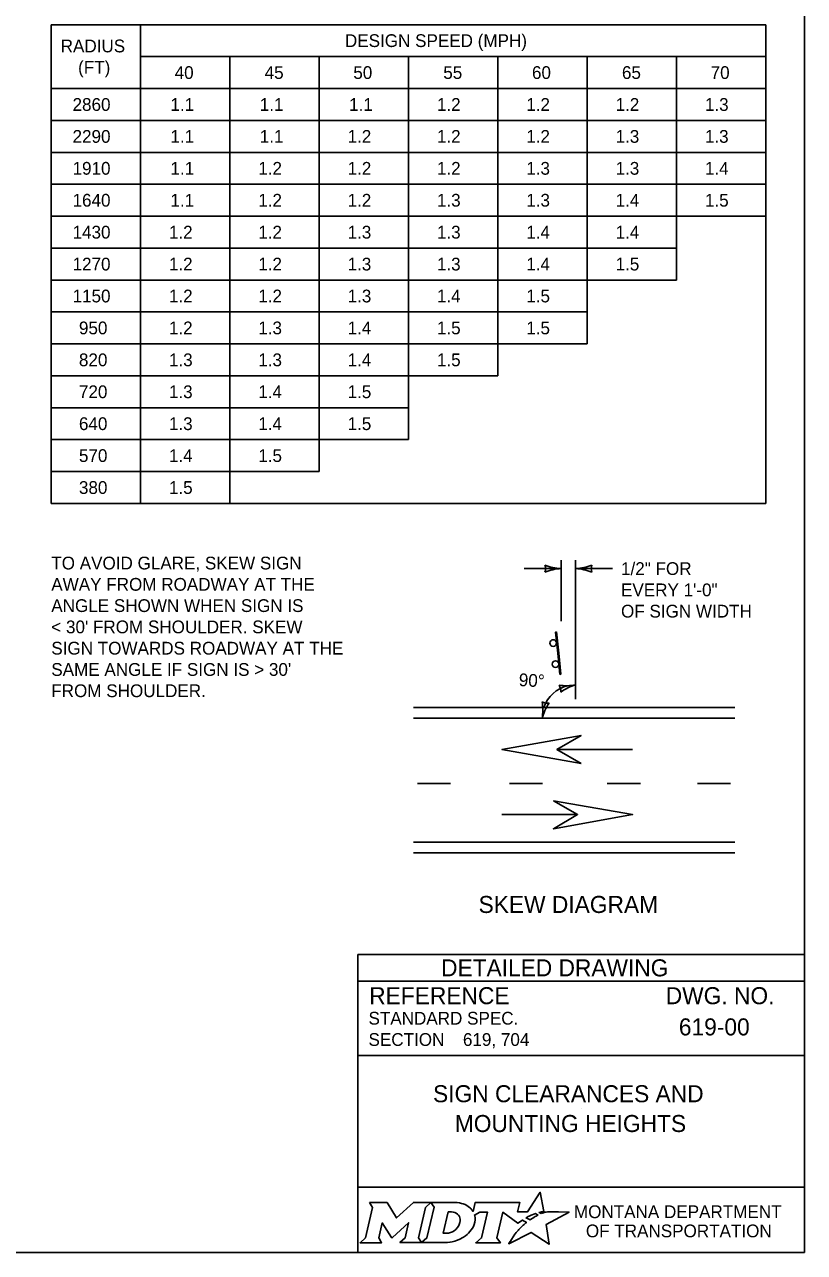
# Model space of a CAD drawing. Extents: x 49991.4 to 50021, y 49987.6 to 50011.4.
# Drawn here: x 50013.08 to 50016.75, y 49987.8 to 49993.57 of the extents above; entities that cross this region are included whole.
import ezdxf

# ---------------------------------------------------------------- set-up
doc = ezdxf.new("R2010")
doc.units = 0
for name, color, linetype in [('Default', 7, 'Continuous'), ('Level 1', 7, 'Continuous'), ('Level 2', 7, 'Continuous'), ('Level 3', 7, 'Continuous'), ('Level 5', 7, 'Continuous')]:
    doc.layers.add(name, color=color, linetype=linetype)

msp = doc.modelspace()

# ---------------------------------------------------------------- linework, layer by layer
at = {"layer": 'Default'}
for points in [[(50015.5126, 49987.9811), (50015.5023, 49987.9867), (50015.5139, 49987.9895), (50015.5255, 49987.9915), (50015.5081, 49988.0816), (50015.4486, 49987.9903), (50015.4013, 49987.9896), (50015.4116, 49988.0337), (50015.2024, 49988.0338), (50015.1923, 49987.9913), (50015.1865, 49987.9996)], [(50014.7056, 49988.0338), (50014.7197, 49988.0104), (50014.6862, 49987.8671), (50014.6605, 49987.8446), (50014.7621, 49987.8446), (50014.7486, 49987.8674), (50014.7648, 49987.9375), (50014.8085, 49987.8685), (50014.8138, 49987.8685), (50014.8889, 49987.938), (50014.8725, 49987.8669), (50014.8478, 49987.8449), (50014.9494, 49987.8449), (50014.9356, 49987.8682), (50014.9688, 49988.0106)], [(50014.9688, 49988.0106), (50014.9941, 49988.0338), (50014.9117, 49988.0338), (50014.8321, 49987.9608), (50014.7876, 49988.0335), (50014.7056, 49988.0338)], [(50015.1077, 49988.0338), (50014.9941, 49988.0338), (50015.0088, 49988.0109), (50014.9749, 49987.8671), (50014.9494, 49987.8449), (50015.06, 49987.8449)], [(50015.1317, 49987.9471), (50015.1305, 49987.939), (50015.1273, 49987.9297), (50015.1231, 49987.9215), (50015.1175, 49987.914), (50015.111, 49987.9071), (50015.1031, 49987.9008), (50015.0948, 49987.8961), (50015.0857, 49987.8922), (50015.0766, 49987.8899), (50015.0674, 49987.889), (50015.0515, 49987.889), (50015.0751, 49987.989), (50015.0911, 49987.989), (50015.0987, 49987.9884), (50015.1063, 49987.9865), (50015.1129, 49987.9835), (50015.119, 49987.9793), (50015.1238, 49987.9743), (50015.1275, 49987.9683), (50015.1302, 49987.9621), (50015.1318, 49987.9547), (50015.1318, 49987.9517), (50015.1317, 49987.9471)], [(50015.1991, 49987.9747), (50015.2237, 49987.9878), (50015.2606, 49987.9878), (50015.232, 49987.8673), (50015.2045, 49987.8446), (50015.3207, 49987.8446), (50015.3037, 49987.8675), (50015.3319, 49987.9877), (50015.4032, 49987.936), (50015.4243, 49987.9511), (50015.444, 49987.9402)], [(50015.3882, 49987.8843), (50015.3729, 49987.8599), (50015.3682, 49987.8524), (50015.3624, 49987.8438), (50015.3601, 49987.8395), (50015.4654, 49987.8926), (50015.5493, 49987.8375), (50015.5362, 49987.9302), (50015.6431, 49987.9886), (50015.5938, 49987.9894), (50015.5637, 49987.9898), (50015.5429, 49987.9901), (50015.5361, 49987.9886), (50015.5312, 49987.9874), (50015.5228, 49987.9851), (50015.5126, 49987.9811)], [(50015.4622, 49987.9535), (50015.4598, 49987.9518), (50015.4415, 49987.9614), (50015.4518, 49987.9671), (50015.4559, 49987.9693), (50015.4645, 49987.9733), (50015.4702, 49987.9759), (50015.4781, 49987.9789), (50015.4854, 49987.9816), (50015.4972, 49987.9742), (50015.4932, 49987.9721), (50015.4886, 49987.9696), (50015.4844, 49987.9674), (50015.4794, 49987.9645), (50015.4775, 49987.9634), (50015.4748, 49987.9618), (50015.4723, 49987.9604), (50015.47, 49987.9588), (50015.4674, 49987.957), (50015.4647, 49987.9552), (50015.4622, 49987.9535)], [(50015.1057, 49987.8522), (50015.1141, 49987.8548), (50015.1271, 49987.8602), (50015.1475, 49987.8712)], [(50015.4021, 49987.9004), (50015.4021, 49987.9004)]]:
    msp.add_lwpolyline(points, dxfattribs=at)
for centre, radius, start, end in [((50015.1308, 49987.9554), 0.0709, 339.53292, 15.85821), ((50015.0868, 49987.9727), 0.1183, 300.91025, 339.13831)]:
    msp.add_arc(centre, radius, start, end, dxfattribs=at)
for centre, major_axis, ratio, start_param, end_param in [((50015.1056, 49987.9864), (0.0834, -0.0037), 0.568097, 0.61298, 1.570796), ((50015.1612, 49987.9937), (0.0361, -0.0295), 0.469099, 1.225588, 1.570796), ((50015.4119, 49987.9106), (-0.0098, -0.0102), 0.016458, 3.141593, 6.279097), ((50015.4329, 49987.9305), (-0.0112, -0.0097), 0.021651, 3.157348, 6.283185), ((50015.0603, 49987.9932), (0, 0.1484), 0.987302, 3.139398, 3.456847), ((50015.3952, 49987.8923), (-0.00694, -0.00806), 0.008222, 0, 3.137361)]:
    msp.add_ellipse(centre, major_axis=major_axis, ratio=ratio, start_param=start_param, end_param=end_param, dxfattribs=at)
at = {"layer": 'Level 1'}
for p, q in [((50015.5795, 49990.7139), (50015.5845, 49990.7145)), ((50015.5795, 49990.7139), (50015.5899, 49990.6148)), ((50015.5801, 49990.714), (50015.5905, 49990.6148)), ((50015.5807, 49990.7141), (50015.5911, 49990.6149)), ((50015.5813, 49990.7141), (50015.5917, 49990.615)), ((50015.582, 49990.7142), (50015.5924, 49990.615)), ((50015.5826, 49990.7143), (50015.593, 49990.6151)), ((50015.5833, 49990.7143), (50015.5937, 49990.6152)), ((50015.5839, 49990.7144), (50015.5943, 49990.6152)), ((50015.5845, 49990.7145), (50015.5949, 49990.6153)), ((50015.5949, 49990.6153), (50015.5899, 49990.6148)), ((50015.5949, 49990.6153), (50015.5899, 49990.6148)), ((50015.6003, 49990.5155), (50015.5899, 49990.6148)), ((50015.6009, 49990.5156), (50015.5905, 49990.6148)), ((50015.6015, 49990.5157), (50015.5911, 49990.6149)), ((50015.6021, 49990.5157), (50015.5917, 49990.615)), ((50015.6028, 49990.5158), (50015.5924, 49990.615)), ((50015.6034, 49990.5159), (50015.593, 49990.6151)), ((50015.6041, 49990.5159), (50015.5937, 49990.6152)), ((50015.6047, 49990.516), (50015.5943, 49990.6152)), ((50015.6053, 49990.5161), (50015.5949, 49990.6153)), ((50015.6003, 49990.5155), (50015.6053, 49990.5161)), ((50016.4225, 49990.359), (50014.9126, 49990.359)), ((50015.6742, 49990.309), (50014.9126, 49990.309)), ((50016.4225, 49990.309), (50015.6742, 49990.309)), ((50015.9421, 49990.1623), (50015.5863, 49990.1623)), ((50014.9308, 49990.0031), (50015.0864, 49990.0031)), ((50015.5188, 49990.0031), (50015.3632, 49990.0031)), ((50015.9788, 49990.0031), (50015.8232, 49990.0031)), ((50016.4026, 49990.0031), (50016.247, 49990.0031)), ((50015.3275, 49989.8566), (50015.6833, 49989.8566)), ((50015.3275, 49989.8562), (50015.6833, 49989.8562)), ((50014.9126, 49989.7263), (50016.4225, 49989.7263)), ((50014.9126, 49989.6763), (50016.4225, 49989.6763)), ((50016.7501, 49989.1988), (50014.6501, 49989.1988)), ((50014.6501, 49989.1988), (50014.6501, 49987.7988)), ((50016.7501, 49989.0738), (50014.6501, 49989.0738)), ((50016.3862, 49988.8587), (50016.3862, 49988.8587)), ((50015.1444, 49988.7993), (50015.1444, 49988.7993)), ((50016.7501, 49988.7238), (50014.6501, 49988.7238)), ((50015.7001, 49988.4747), (50015.7001, 49988.4747))]:
    msp.add_line(p, q, dxfattribs=at)
for points in [[(49999.3835, 49998.9992), (50016.7501, 49998.9992), (50016.7501, 49987.7988), (49999.3835, 49987.7988)], [(50015.7001, 49990.0963), (50015.3277, 49990.1619), (50015.7001, 49990.2279), (50015.5865, 49990.1619)], [(50015.5697, 49989.9218), (50015.9421, 49989.8562), (50015.5697, 49989.7902), (50015.6833, 49989.8562)]]:
    msp.add_lwpolyline(points, close=True, dxfattribs=at)
for centre in [(50015.5689, 49990.6627), (50015.5793, 49990.5634)]:
    msp.add_circle(centre, 0.0156, dxfattribs=at)
at = {"layer": 'Level 2'}
for p, q in [((50013.209, 49993.5684), (50016.569, 49993.5684)), ((50013.209, 49993.5684), (50013.209, 49991.3184)), ((50013.629, 49993.5684), (50013.629, 49991.3184)), ((50016.569, 49993.5684), (50016.569, 49991.3184)), ((50013.629, 49993.4184), (50016.569, 49993.4184)), ((50014.049, 49993.4184), (50014.049, 49991.3184)), ((50014.469, 49993.4184), (50014.469, 49991.4684)), ((50014.889, 49993.4184), (50014.889, 49991.6184)), ((50015.309, 49993.4184), (50015.309, 49991.9184)), ((50015.729, 49993.4184), (50015.729, 49992.0684)), ((50016.149, 49993.4184), (50016.149, 49992.3684)), ((50013.209, 49993.2684), (50016.569, 49993.2684)), ((50013.209, 49993.1184), (50016.569, 49993.1184)), ((50013.209, 49992.9684), (50016.569, 49992.9684)), ((50013.209, 49992.8184), (50016.569, 49992.8184)), ((50013.209, 49992.6684), (50016.569, 49992.6684)), ((50016.569, 49992.6684), (50016.149, 49992.6684)), ((50016.149, 49992.6684), (50016.149, 49992.3684)), ((50016.569, 49991.3184), (50016.569, 49992.6684)), ((50013.209, 49992.5184), (50016.149, 49992.5184)), ((50013.209, 49992.3684), (50016.149, 49992.3684)), ((50016.149, 49992.3684), (50015.729, 49992.3684)), ((50015.729, 49992.3684), (50015.729, 49992.0684)), ((50013.209, 49992.2184), (50015.729, 49992.2184)), ((50013.209, 49992.0684), (50015.729, 49992.0684)), ((50015.729, 49992.0684), (50015.309, 49992.0684)), ((50015.309, 49992.0684), (50015.309, 49991.9184)), ((50013.209, 49991.9184), (50015.309, 49991.9184)), ((50015.309, 49991.9184), (50014.889, 49991.9184)), ((50014.889, 49991.9184), (50014.889, 49991.6184)), ((50013.209, 49991.7684), (50014.889, 49991.7684)), ((50013.209, 49991.6184), (50014.889, 49991.6184)), ((50014.889, 49991.6184), (50014.469, 49991.6184)), ((50014.469, 49991.6184), (50014.469, 49991.4684)), ((50013.209, 49991.4684), (50014.469, 49991.4684)), ((50014.469, 49991.4684), (50014.049, 49991.4684)), ((50014.049, 49991.4684), (50014.049, 49991.3184)), ((50013.209, 49991.3184), (50016.569, 49991.3184)), ((50014.049, 49991.3184), (50016.569, 49991.3184)), ((50016.4225, 49989.7263), (50016.4225, 49989.7263))]:
    msp.add_line(p, q, dxfattribs=at)
at = {"layer": 'Level 3'}
for p, q in [((50015.6059, 49990.7658), (50015.6059, 49991.0524)), ((50015.6743, 49990.399), (50015.6743, 49991.0524)), ((50015.4325, 49991.0124), (50015.6059, 49991.0124)), ((50015.6743, 49991.0124), (50015.8477, 49991.0124))]:
    msp.add_line(p, q, dxfattribs=at)
for centre, radius, start, end in [((50015.6151, 49991.2345), 0.2223, 247.45601, 267.63952), ((50015.4777, 49991.0124), 0.0548, 342.13882, 17.86118), ((50015.6628, 49991.2451), 0.233, 272.82731, 292.07716), ((50015.8026, 49991.0124), 0.0548, 162.13882, 197.86118), ((50015.6174, 49990.7797), 0.233, 92.82731, 112.07716), ((50015.6652, 49990.7903), 0.2223, 67.45601, 87.63952), ((50015.6743, 49990.309), 0.1574, 103.39391, 161.48029), ((50015.6303, 49990.6843), 0.2223, 261.22568, 281.40919), ((50015.5498, 49990.4359), 0.0548, 355.90849, 31.63085), ((50015.7409, 49990.2431), 0.233, 106.59698, 125.84683), ((50015.544, 49990.4343), 0.0548, 239.92677, 275.64914), ((50015.287, 49990.347), 0.233, 350.61527, 9.86512), ((50015.7321, 49990.2531), 0.2223, 145.24397, 165.42747)]:
    msp.add_arc(centre, radius, start, end, dxfattribs=at)
at = {"layer": 'Level 5'}
for p, q in [((50016.7501, 49989.1988), (50014.6501, 49989.1988)), ((50014.6501, 49989.1988), (50014.6501, 49987.7988)), ((50016.7501, 49989.0738), (50014.6501, 49989.0738)), ((50016.3862, 49988.8587), (50016.3862, 49988.8587)), ((50015.1444, 49988.7993), (50015.1444, 49988.7993)), ((50016.7501, 49988.7238), (50014.6501, 49988.7238)), ((50015.7001, 49988.4747), (50015.7001, 49988.4747)), ((50016.7501, 49988.1057), (50014.6501, 49988.1057))]:
    msp.add_line(p, q, dxfattribs=at)

# ---------------------------------------------------------------- texts
at = {"layer": 'Default'}
for s, p in [('MONTANA DEPARTMENT', (50015.6663, 49987.96)), ('OF TRANSPORTATION', (50015.7225, 49987.87))]:
    msp.add_text(s, height=0.06, dxfattribs=at).set_placement(p)
at = {"layer": 'Level 1'}
for s, height, p in [('DETAILED DRAWING', 0.0799, (50015.0418, 49989.0963)), ('REFERENCE', 0.08, (50014.7037, 49988.9654)), ('DWG. NO.', 0.08, (50016.0979, 49988.9654)), ('STANDARD SPEC.', 0.06, (50014.7004, 49988.8694)), ('SECTION', 0.06, (50014.7004, 49988.7694))]:
    msp.add_text(s, height=height, dxfattribs=at).set_placement(p)
at = {"layer": 'Level 2'}
for s, height, p in [('DESIGN SPEED (MPH)', 0.06, (50014.5896, 49993.4634)), ('RADIUS', 0.06, (50013.2532, 49993.4384)), ('(FT)', 0.06, (50013.335, 49993.3384)), ('40', 0.06, (50013.789, 49993.3134)), ('45', 0.06, (50014.212, 49993.3134)), ('50', 0.06, (50014.629, 49993.3134)), ('55', 0.06, (50015.052, 49993.3134)), ('60', 0.06, (50015.469, 49993.3134)), ('65', 0.06, (50015.892, 49993.3134)), ('70', 0.06, (50016.309, 49993.3134)), ('2860', 0.06, (50013.309, 49993.1634)), ('1.1', 0.06, (50013.7693, 49993.1634)), ('1.1', 0.06, (50014.1893, 49993.1634)), ('1.1', 0.06, (50014.6093, 49993.1634)), ('1.2', 0.06, (50015.022, 49993.1634)), ('1.2', 0.06, (50015.442, 49993.1634)), ('1.2', 0.06, (50015.862, 49993.1634)), ('1.3', 0.06, (50016.282, 49993.1634)), ('2290', 0.06, (50013.309, 49993.0134)), ('1.1', 0.06, (50013.7693, 49993.0134)), ('1.1', 0.06, (50014.1893, 49993.0134)), ('1.2', 0.06, (50014.602, 49993.0134)), ('1.2', 0.06, (50015.022, 49993.0134)), ('1.2', 0.06, (50015.442, 49993.0134)), ('1.3', 0.06, (50015.862, 49993.0134)), ('1.3', 0.06, (50016.282, 49993.0134)), ('1910', 0.06, (50013.309, 49992.8634)), ('1.1', 0.06, (50013.7694, 49992.8634)), ('1.2', 0.06, (50014.182, 49992.8634)), ('1.2', 0.06, (50014.602, 49992.8634)), ('1.2', 0.06, (50015.022, 49992.8634)), ('1.3', 0.06, (50015.442, 49992.8634)), ('1.3', 0.06, (50015.862, 49992.8634)), ('1.4', 0.06, (50016.282, 49992.8634)), ('1640', 0.06, (50013.309, 49992.7134)), ('1.1', 0.06, (50013.7693, 49992.7134)), ('1.2', 0.06, (50014.182, 49992.7134)), ('1.2', 0.06, (50014.602, 49992.7134)), ('1.3', 0.06, (50015.0221, 49992.7134)), ('1.3', 0.06, (50015.442, 49992.7134)), ('1.4', 0.06, (50015.862, 49992.7134)), ('1.5', 0.06, (50016.2821, 49992.7134)), ('1430', 0.06, (50013.309, 49992.5634)), ('1.2', 0.06, (50013.762, 49992.5634)), ('1.2', 0.06, (50014.182, 49992.5634)), ('1.3', 0.06, (50014.602, 49992.5634)), ('1.3', 0.06, (50015.022, 49992.5634)), ('1.4', 0.06, (50015.442, 49992.5634)), ('1.4', 0.06, (50015.862, 49992.5634)), ('1270', 0.06, (50013.309, 49992.4134)), ('1.2', 0.06, (50013.762, 49992.4134)), ('1.2', 0.06, (50014.182, 49992.4134)), ('1.3', 0.06, (50014.602, 49992.4134)), ('1.3', 0.06, (50015.022, 49992.4134)), ('1.4', 0.06, (50015.4421, 49992.4134)), ('1.5', 0.06, (50015.862, 49992.4134)), ('1150', 0.06, (50013.309, 49992.2634)), ('1.2', 0.06, (50013.762, 49992.2634)), ('1.2', 0.06, (50014.182, 49992.2634)), ('1.3', 0.06, (50014.6021, 49992.2634)), ('1.4', 0.06, (50015.022, 49992.2634)), ('1.5', 0.06, (50015.4421, 49992.2634)), ('950', 0.06, (50013.339, 49992.1134)), ('1.2', 0.06, (50013.762, 49992.1134)), ('1.3', 0.06, (50014.182, 49992.1134)), ('1.4', 0.06, (50014.6021, 49992.1134)), ('1.5', 0.06, (50015.022, 49992.1134)), ('1.5', 0.06, (50015.442, 49992.1134)), ('820', 0.06, (50013.339, 49991.9634)), ('1.3', 0.06, (50013.7621, 49991.9634)), ('1.3', 0.06, (50014.182, 49991.9634)), ('1.4', 0.06, (50014.602, 49991.9634)), ('1.5', 0.06, (50015.022, 49991.9634)), ('720', 0.06, (50013.339, 49991.8134)), ('1.3', 0.06, (50013.762, 49991.8134)), ('1.4', 0.06, (50014.182, 49991.8134)), ('1.5', 0.06, (50014.602, 49991.8134)), ('640', 0.06, (50013.339, 49991.6634)), ('1.3', 0.06, (50013.762, 49991.6634)), ('1.4', 0.06, (50014.182, 49991.6634)), ('1.5', 0.06, (50014.602, 49991.6634)), ('570', 0.06, (50013.339, 49991.5134)), ('1.4', 0.06, (50013.762, 49991.5134)), ('1.5', 0.06, (50014.182, 49991.5134)), ('380', 0.06, (50013.339, 49991.3634)), ('1.5', 0.06, (50013.762, 49991.3634)), ('TO AVOID GLARE, SKEW SIGN', 0.06, (50013.209, 49991.0084)), ('1/2" FOR ', 0.06, (50015.8877, 49990.9824)), ('AWAY FROM ROADWAY AT THE ', 0.06, (50013.209, 49990.9084)), ('EVERY 1\'-0" ', 0.06, (50015.8877, 49990.8824)), ('ANGLE SHOWN WHEN SIGN IS', 0.06, (50013.209, 49990.8084)), ('OF SIGN WIDTH', 0.06, (50015.8877, 49990.7824)), ("< 30' FROM SHOULDER. SKEW ", 0.06, (50013.209, 49990.7084)), ('SIGN TOWARDS ROADWAY AT THE', 0.06, (50013.209, 49990.6084)), ("SAME ANGLE IF SIGN IS > 30' ", 0.06, (50013.209, 49990.5084)), ('FROM SHOULDER.', 0.06, (50013.209, 49990.4084)), ('SKEW DIAGRAM', 0.08, (50015.2179, 49989.3941)), ('619-00', 0.08, (50016.1596, 49988.8187)), ('619, 704', 0.06, (50015.1444, 49988.7693)), ('SIGN CLEARANCES AND', 0.08, (50015.0039, 49988.5047)), ('MOUNTING HEIGHTS', 0.08, (50015.1062, 49988.3647))]:
    msp.add_text(s, height=height, dxfattribs=at).set_placement(p)
msp.add_text('90°', height=0.06, rotation=357, dxfattribs=at).set_placement((50015.4057, 49990.4605))

doc.saveas('drawing.dxf')
